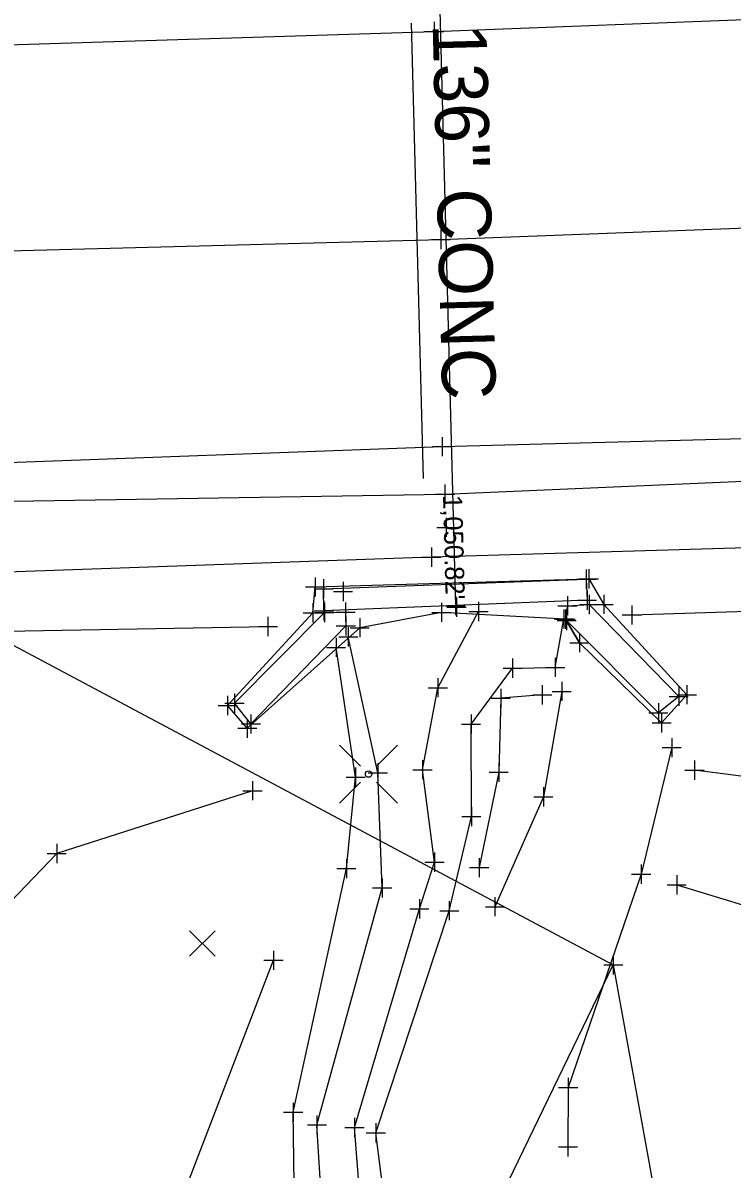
# Model space of a CAD drawing. Extents: x 211013 to 211654, y 505587 to 505872.
# Drawn here: x 211288.2 to 211325.2, y 505674.5 to 505734.3 of the extents above; entities that cross this region are included whole.
import ezdxf

# ---------------------------------------------------------------- set-up
doc = ezdxf.new("R2010")
doc.units = 0
for name, color, linetype in [('_CIVIL_CONSTRUCTION', 7, 'Continuous'), ('AP_P_PCI_Pavement', 7, 'Continuous'), ('BR_P_Gen_Porous_Backfill', 7, 'Continuous'), ('BR_X_Rail_Centerline', 7, 'Continuous'), ('DR_X_Storm_Sewer', 7, 'Continuous'), ('DR_X_Text', 7, 'Continuous'), ('DV_X_Property_Line', 7, 'Continuous'), ('DV_X_Section_VMS_Line', 7, 'Continuous'), ('GE_X_Alignment_1000_Curve_Data', 7, 'Continuous'), ('GE_X_Alignment_100_Stations', 7, 'Continuous'), ('GE_X_Alignment_500_Curve_Data', 7, 'Continuous'), ('GE_X_Alignment_500_Stations', 7, 'Continuous'), ('PM_X_CL_Pass_Proh_Lt', 7, 'Continuous'), ('PM_X_Edge_Line', 7, 'Continuous'), ('RW_P_Esmt_SH', 7, 'Continuous'), ('RW_X_Esmt_SH', 7, 'Continuous'), ('SC_Scratch1', 7, 'Continuous'), ('SC_Scratch10', 7, 'Continuous'), ('SC_Scratch3', 7, 'Continuous'), ('SV_X_Terrain_Break_Line', 7, 'Continuous')]:
    doc.layers.add(name, color=color, linetype=linetype)

msp = doc.modelspace()

# ---------------------------------------------------------------- linework, layer by layer
at = {"layer": '_CIVIL_CONSTRUCTION'}
msp.add_lwpolyline([(211299.916, 505697.512), (211298.892, 505698.697), (211303.335, 505703.534), (211303.459, 505704.883), (211317.723, 505705.313), (211318.503, 505703.976), (211322.84, 505699.265), (211321.522, 505697.798), (211317.242, 505701.978), (211316.512, 505703.201), (211310.041, 505703.559), (211305.778, 505702.757)], close=True, dxfattribs=at)
at = {"layer": 'AP_P_PCI_Pavement'}
for points in [[(211268.661, 505610.595), (211277.693, 505622.388), (211291.679, 505636.827), (211300.374, 505649.703), (211302.563, 505658.8), (211302.312, 505677.481), (211305.082, 505690.193), (211305.564, 505694.97), (211304.545, 505701.731)], [(211278.617, 505602.944), (211284.156, 505615.606), (211296.4, 505628.157), (211306.009, 505644.49), (211310.431, 505653.543), (211313.281, 505673.354), (211319.004, 505685.175)]]:
    msp.add_lwpolyline(points, dxfattribs=at)
at = {"layer": 'BR_P_Gen_Porous_Backfill'}
msp.add_lwpolyline([(211014.599, 505713.748), (211060.117, 505715.292), (211110.477, 505716.76), (211159.605, 505717.981), (211200.363, 505719.769), (211209.599, 505719.607), (211259.602, 505721.26), (211285.444, 505722.36), (211310.014, 505723.011), (211334.642, 505723.955), (211359.491, 505724.699), (211409.159, 505726.492), (211459.682, 505727.943), (211509.305, 505729.663), (211559.474, 505731.149), (211610.495, 505732.771), (211648.152, 505734.06)], dxfattribs=at)
at = {"layer": 'BR_X_Rail_Centerline'}
for p, q in [((211286.353, 505702.567), (211319.004, 505685.175)), ((211319.004, 505685.175), (211322.15, 505667.715))]:
    msp.add_line(p, q, dxfattribs=at)
at = {"layer": 'DR_X_Storm_Sewer'}
msp.add_line((211309.709, 505744.552), (211310.772, 505703.905), dxfattribs=at)
at = {"layer": 'DR_X_Text'}
msp.add_line((211309.098, 505710.538), (211308.477, 505734.29), dxfattribs=at)
at = {"layer": 'DV_X_Property_Line'}
for p, q in [((211335.584, 505707.206), (211309.514, 505706.438)), ((211309.514, 505706.438), (211285.253, 505705.579))]:
    msp.add_line(p, q, dxfattribs=at)
at = {"layer": 'DV_X_Section_VMS_Line'}
for p, q in [((211309.664, 505734.365), (211309.664, 505733.365)), ((211309.664, 505734.365), (211309.664, 505733.365)), ((211309.164, 505733.865), (211310.164, 505733.865)), ((211309.164, 505733.865), (211310.164, 505733.865)), ((211309.664, 505733.865), (211309.664, 505733.865)), ((211309.664, 505733.865), (211309.664, 505733.865)), ((211310.014, 505723.511), (211310.014, 505722.511)), ((211310.014, 505723.511), (211310.014, 505722.511)), ((211309.514, 505723.011), (211310.514, 505723.011)), ((211309.514, 505723.011), (211310.514, 505723.011)), ((211310.014, 505723.011), (211310.014, 505723.011)), ((211310.014, 505723.011), (211310.014, 505723.011)), ((211310.077, 505712.707), (211310.077, 505711.707)), ((211310.077, 505712.707), (211310.077, 505711.707)), ((211309.577, 505712.207), (211310.577, 505712.207)), ((211309.577, 505712.207), (211310.577, 505712.207)), ((211310.077, 505712.207), (211310.077, 505712.207)), ((211310.077, 505712.207), (211310.077, 505712.207)), ((211310.225, 505710.223), (211310.225, 505709.223)), ((211309.725, 505709.723), (211310.725, 505709.723)), ((211310.225, 505709.723), (211310.225, 505709.723)), ((211310.292, 505708.492), (211310.292, 505707.492)), ((211309.792, 505707.992), (211310.792, 505707.992)), ((211310.292, 505707.992), (211310.292, 505707.992)), ((211309.514, 505706.938), (211309.514, 505705.938)), ((211309.014, 505706.438), (211310.014, 505706.438)), ((211309.514, 505706.438), (211309.514, 505706.438)), ((211303.459, 505705.383), (211303.459, 505704.383)), ((211303.897, 505705.288), (211303.897, 505704.288)), ((211317.088, 505705.295), (211318.088, 505705.295)), ((211317.223, 505705.313), (211318.223, 505705.313)), ((211317.588, 505705.795), (211317.588, 505704.795)), ((211317.588, 505705.295), (211317.588, 505705.295)), ((211317.723, 505705.813), (211317.723, 505704.813)), ((211317.723, 505705.313), (211317.723, 505705.313)), ((211302.959, 505704.883), (211303.959, 505704.883)), ((211303.397, 505704.788), (211304.397, 505704.788)), ((211303.459, 505704.883), (211303.459, 505704.883)), ((211303.897, 505704.788), (211303.897, 505704.788)), ((211304.908, 505705.149), (211304.908, 505704.149)), ((211317.633, 505704.698), (211317.633, 505703.698)), ((211303.907, 505704.142), (211303.907, 505703.142)), ((211304.408, 505704.649), (211305.408, 505704.649)), ((211304.908, 505704.649), (211304.908, 505704.649)), ((211310.824, 505704.334), (211310.824, 505703.334)), ((211311.977, 505704.105), (211311.977, 505703.105)), ((211316.61, 505704.406), (211316.61, 505703.406)), ((211317.133, 505704.198), (211318.133, 505704.198)), ((211317.633, 505704.198), (211317.633, 505704.198)), ((211317.752, 505704.471), (211317.752, 505703.471)), ((211318.503, 505704.476), (211318.503, 505703.476)), ((211302.835, 505703.534), (211303.835, 505703.534)), ((211303.335, 505704.034), (211303.335, 505703.034)), ((211303.335, 505703.534), (211303.335, 505703.534)), ((211303.407, 505703.642), (211304.407, 505703.642)), ((211303.45, 505703.556), (211304.45, 505703.556)), ((211303.907, 505703.642), (211303.907, 505703.642)), ((211303.95, 505704.056), (211303.95, 505703.056)), ((211303.95, 505703.556), (211303.95, 505703.556)), ((211304.533, 505703.568), (211305.533, 505703.568)), ((211305.033, 505704.068), (211305.033, 505703.068)), ((211305.033, 505703.568), (211305.033, 505703.568)), ((211309.541, 505703.559), (211310.541, 505703.559)), ((211310.041, 505704.059), (211310.041, 505703.059)), ((211310.041, 505703.559), (211310.041, 505703.559)), ((211310.324, 505703.834), (211311.324, 505703.834)), ((211310.824, 505703.834), (211310.824, 505703.834)), ((211311.477, 505703.605), (211312.477, 505703.605)), ((211311.977, 505703.605), (211311.977, 505703.605)), ((211316.11, 505703.906), (211317.11, 505703.906)), ((211316.416, 505703.715), (211316.416, 505702.715)), ((211316.512, 505703.701), (211316.512, 505702.701)), ((211316.568, 505703.629), (211316.568, 505702.629)), ((211316.61, 505703.906), (211316.61, 505703.906)), ((211317.252, 505703.971), (211318.252, 505703.971)), ((211317.752, 505703.971), (211317.752, 505703.971)), ((211318.003, 505703.976), (211319.003, 505703.976)), ((211318.503, 505703.976), (211318.503, 505703.976)), ((211319.968, 505703.925), (211319.968, 505702.925)), ((211300.992, 505703.322), (211300.992, 505702.322)), ((211305.058, 505703.35), (211305.058, 505702.35)), ((211305.778, 505703.257), (211305.778, 505702.257)), ((211315.916, 505703.215), (211316.916, 505703.215)), ((211316.012, 505703.201), (211317.012, 505703.201)), ((211316.068, 505703.129), (211317.068, 505703.129)), ((211316.416, 505703.215), (211316.416, 505703.215)), ((211316.512, 505703.201), (211316.512, 505703.201)), ((211316.568, 505703.129), (211316.568, 505703.129)), ((211319.468, 505703.425), (211320.468, 505703.425)), ((211319.968, 505703.425), (211319.968, 505703.425)), ((211300.492, 505702.822), (211301.492, 505702.822)), ((211300.992, 505702.822), (211300.992, 505702.822)), ((211304.558, 505702.85), (211305.558, 505702.85)), ((211305.058, 505702.85), (211305.058, 505702.85)), ((211305.183, 505702.782), (211305.183, 505701.782)), ((211305.278, 505702.757), (211306.278, 505702.757)), ((211305.778, 505702.757), (211305.778, 505702.757)), ((211317.242, 505702.478), (211317.242, 505701.478)), ((211304.045, 505701.731), (211305.045, 505701.731)), ((211304.545, 505702.231), (211304.545, 505701.231)), ((211304.545, 505701.731), (211304.545, 505701.731)), ((211304.683, 505702.282), (211305.683, 505702.282)), ((211305.183, 505702.282), (211305.183, 505702.282)), ((211316.742, 505701.978), (211317.742, 505701.978)), ((211317.242, 505701.978), (211317.242, 505701.978)), ((211313.752, 505701.151), (211313.752, 505700.151)), ((211315.976, 505701.191), (211315.976, 505700.191)), ((211313.252, 505700.651), (211314.252, 505700.651)), ((211313.752, 505700.651), (211313.752, 505700.651)), ((211315.476, 505700.691), (211316.476, 505700.691)), ((211315.976, 505700.691), (211315.976, 505700.691)), ((211309.856, 505700.129), (211309.856, 505699.129)), ((211316.314, 505699.937), (211316.314, 505698.937)), ((211299.25, 505699.322), (211299.25, 505698.322)), ((211309.356, 505699.629), (211310.356, 505699.629)), ((211309.856, 505699.629), (211309.856, 505699.629)), ((211313.131, 505699.577), (211313.131, 505698.577)), ((211315.3, 505699.755), (211315.3, 505698.755)), ((211315.814, 505699.437), (211316.814, 505699.437)), ((211316.314, 505699.437), (211316.314, 505699.437)), ((211322.413, 505699.677), (211322.413, 505698.677)), ((211322.84, 505699.765), (211322.84, 505698.765)), ((211298.75, 505698.822), (211299.75, 505698.822)), ((211298.892, 505699.197), (211298.892, 505698.197)), ((211299.25, 505698.822), (211299.25, 505698.822)), ((211312.631, 505699.077), (211313.631, 505699.077)), ((211313.131, 505699.077), (211313.131, 505699.077)), ((211314.8, 505699.255), (211315.8, 505699.255)), ((211315.3, 505699.255), (211315.3, 505699.255)), ((211321.354, 505698.82), (211321.354, 505697.82)), ((211321.913, 505699.177), (211322.913, 505699.177)), ((211322.34, 505699.265), (211323.34, 505699.265)), ((211322.413, 505699.177), (211322.413, 505699.177)), ((211322.84, 505699.265), (211322.84, 505699.265)), ((211298.392, 505698.697), (211299.392, 505698.697)), ((211298.892, 505698.697), (211298.892, 505698.697)), ((211300.106, 505698.239), (211300.106, 505697.239)), ((211311.583, 505698.233), (211311.583, 505697.233)), ((211320.854, 505698.32), (211321.854, 505698.32)), ((211321.354, 505698.32), (211321.354, 505698.32)), ((211321.522, 505698.298), (211321.522, 505697.298)), ((211299.416, 505697.512), (211300.416, 505697.512)), ((211299.606, 505697.739), (211300.606, 505697.739)), ((211299.916, 505698.012), (211299.916, 505697.012)), ((211299.916, 505697.512), (211299.916, 505697.512)), ((211300.106, 505697.739), (211300.106, 505697.739)), ((211311.083, 505697.733), (211312.083, 505697.733)), ((211311.583, 505697.733), (211311.583, 505697.733)), ((211321.022, 505697.798), (211322.022, 505697.798)), ((211321.522, 505697.798), (211321.522, 505697.798)), ((211322.047, 505697.005), (211322.047, 505696.005)), ((211321.547, 505696.505), (211322.547, 505696.505)), ((211322.047, 505696.505), (211322.047, 505696.505)), ((211309.052, 505695.852), (211309.052, 505694.852)), ((211313.027, 505695.718), (211313.027, 505694.718)), ((211323.24, 505695.828), (211323.24, 505694.828)), ((211305.564, 505695.47), (211305.564, 505694.47)), ((211306.226, 505695.195), (211307.226, 505695.195)), ((211306.726, 505695.695), (211306.726, 505694.695)), ((211306.726, 505695.195), (211306.726, 505695.195)), ((211308.552, 505695.352), (211309.552, 505695.352)), ((211309.052, 505695.352), (211309.052, 505695.352)), ((211312.527, 505695.218), (211313.527, 505695.218)), ((211313.027, 505695.218), (211313.027, 505695.218)), ((211322.74, 505695.328), (211323.74, 505695.328)), ((211323.24, 505695.328), (211323.24, 505695.328)), ((211300.189, 505694.755), (211300.189, 505693.755)), ((211305.064, 505694.97), (211306.064, 505694.97)), ((211305.564, 505694.97), (211305.564, 505694.97)), ((211299.689, 505694.255), (211300.689, 505694.255)), ((211300.189, 505694.255), (211300.189, 505694.255)), ((211314.855, 505693.94), (211315.855, 505693.94)), ((211315.355, 505694.44), (211315.355, 505693.44)), ((211315.355, 505693.94), (211315.355, 505693.94)), ((211311.603, 505693.404), (211311.603, 505692.404)), ((211311.103, 505692.904), (211312.103, 505692.904)), ((211311.603, 505692.904), (211311.603, 505692.904)), ((211289.479, 505690.984), (211290.479, 505690.984)), ((211289.979, 505691.484), (211289.979, 505690.484)), ((211289.979, 505690.984), (211289.979, 505690.984)), ((211309.682, 505691.026), (211309.682, 505690.026)), ((211305.082, 505690.693), (211305.082, 505689.693)), ((211309.182, 505690.526), (211310.182, 505690.526)), ((211309.682, 505690.526), (211309.682, 505690.526)), ((211312.009, 505690.744), (211312.009, 505689.744)), ((211320.459, 505690.403), (211320.459, 505689.403)), ((211304.582, 505690.193), (211305.582, 505690.193)), ((211305.082, 505690.193), (211305.082, 505690.193)), ((211311.509, 505690.244), (211312.509, 505690.244)), ((211312.009, 505690.244), (211312.009, 505690.244)), ((211319.959, 505689.903), (211320.959, 505689.903)), ((211320.459, 505689.903), (211320.459, 505689.903)), ((211322.311, 505689.843), (211322.311, 505688.843)), ((211306.447, 505689.181), (211307.447, 505689.181)), ((211306.947, 505689.681), (211306.947, 505688.681)), ((211306.947, 505689.181), (211306.947, 505689.181)), ((211321.811, 505689.343), (211322.811, 505689.343)), ((211322.311, 505689.343), (211322.311, 505689.343)), ((211308.888, 505688.595), (211308.888, 505687.595)), ((211312.833, 505688.705), (211312.833, 505687.705)), ((211308.388, 505688.095), (211309.388, 505688.095)), ((211308.888, 505688.095), (211308.888, 505688.095)), ((211309.952, 505687.996), (211310.952, 505687.996)), ((211310.452, 505688.496), (211310.452, 505687.496)), ((211310.452, 505687.996), (211310.452, 505687.996)), ((211312.333, 505688.205), (211313.333, 505688.205)), ((211312.833, 505688.205), (211312.833, 505688.205)), ((211301.283, 505685.911), (211301.283, 505684.911)), ((211319.004, 505685.675), (211319.004, 505684.675)), ((211300.783, 505685.411), (211301.783, 505685.411)), ((211301.283, 505685.411), (211301.283, 505685.411)), ((211318.504, 505685.175), (211319.504, 505685.175)), ((211319.004, 505685.175), (211319.004, 505685.175)), ((211316.652, 505679.278), (211316.652, 505678.278)), ((211316.152, 505678.778), (211317.152, 505678.778)), ((211316.652, 505678.778), (211316.652, 505678.778)), ((211302.312, 505677.981), (211302.312, 505676.981)), ((211301.812, 505677.481), (211302.812, 505677.481)), ((211302.312, 505677.481), (211302.312, 505677.481)), ((211303.549, 505677.317), (211303.549, 505676.317)), ((211305.511, 505677.184), (211305.511, 505676.184)), ((211303.049, 505676.817), (211304.049, 505676.817)), ((211303.549, 505676.817), (211303.549, 505676.817)), ((211305.011, 505676.684), (211306.011, 505676.684)), ((211305.511, 505676.684), (211305.511, 505676.684)), ((211306.622, 505676.904), (211306.622, 505675.904)), ((211306.122, 505676.404), (211307.122, 505676.404)), ((211306.622, 505676.404), (211306.622, 505676.404)), ((211316.64, 505676.18), (211316.64, 505675.18)), ((211316.14, 505675.68), (211317.14, 505675.68)), ((211316.64, 505675.68), (211316.64, 505675.68))]:
    msp.add_line(p, q, dxfattribs=at)
at = {"layer": 'GE_X_Alignment_1000_Curve_Data'}
msp.add_lwpolyline([(211273.121, 505606.086), (211279.731, 505619.542), (211294.465, 505632.777), (211303.74, 505647.431), (211307.255, 505654.162), (211305.511, 505676.684), (211308.888, 505688.095), (211309.682, 505690.526), (211309.052, 505695.352), (211309.856, 505699.629), (211311.977, 505703.605)], dxfattribs=at)
at = {"layer": 'GE_X_Alignment_100_Stations'}
msp.add_line((211316.512, 505703.201), (211317.242, 505701.978), dxfattribs=at)
for points in [[(211647.318, 505706.799), (211627.344, 505705.682), (211610.092, 505706.34), (211575.017, 505706.539), (211552.648, 505705.843), (211519.602, 505699.232), (211499.135, 505697.96), (211475.775, 505696.23), (211461, 505699.162), (211420.091, 505696.365), (211400.739, 505694.843), (211371.166, 505695.886), (211354.307, 505694.819), (211334.256, 505693.898), (211323.24, 505695.328)], [(211319.968, 505703.425), (211335.359, 505703.922), (211358.547, 505705.427)], [(211213.935, 505701.665), (211234.368, 505701.356), (211259.558, 505702.48), (211286.353, 505702.567), (211300.992, 505702.822)], [(211316.314, 505699.437), (211315.355, 505693.94), (211312.833, 505688.205)], [(211315.3, 505699.255), (211313.131, 505699.077), (211313.027, 505695.218), (211312.009, 505690.244)], [(211322.047, 505696.505), (211320.459, 505689.903), (211316.652, 505678.778), (211316.64, 505675.68)], [(211300.189, 505694.255), (211289.979, 505690.984), (211282.308, 505682.988), (211268.748, 505680.552), (211247.685, 505678.308), (211236.738, 505676.753), (211227.288, 505673.299), (211219.174, 505669.2), (211212.291, 505658.054), (211212.19, 505645.024), (211215.908, 505636.829), (211217.344, 505628.443), (211218.512, 505613.393)], [(211322.311, 505689.343), (211333.961, 505685.806), (211349.341, 505686.838)], [(211281.328, 505628.196), (211283.332, 505634.721), (211288.956, 505646.146), (211290.89, 505656.543), (211295.544, 505670.479), (211301.283, 505685.411)]]:
    msp.add_lwpolyline(points, dxfattribs=at)
at = {"layer": 'GE_X_Alignment_500_Curve_Data'}
for points in [[(211014.945, 505724.377), (211059.004, 505725.803), (211109.78, 505727.197), (211159.509, 505728.763), (211208.815, 505730.577), (211259.797, 505732.066), (211285.147, 505733.092), (211309.664, 505733.865), (211334.856, 505734.829), (211359.193, 505735.686), (211410.228, 505737.375), (211459.705, 505738.838), (211509.757, 505740.373), (211559.969, 505741.955), (211609.77, 505743.952), (211648.342, 505745.167)], [(211015.177, 505702.304), (211059.888, 505703.863), (211110.083, 505705.463), (211159.907, 505707.213), (211209.998, 505708.767), (211260.133, 505710.635), (211285.525, 505711.304), (211310.077, 505712.207), (211335.574, 505712.892), (211359.345, 505713.874), (211409.235, 505715.384), (211460.17, 505716.905), (211509.667, 505718.762), (211560, 505720.306), (211609.437, 505722.106), (211648.414, 505723.359)]]:
    msp.add_lwpolyline(points, dxfattribs=at)
at = {"layer": 'GE_X_Alignment_500_Stations'}
msp.add_lwpolyline([(211015.256, 505700.037), (211059.934, 505701.398), (211110.755, 505702.874), (211160.108, 505704.521), (211209.982, 505706.264), (211260.298, 505708.404), (211285.531, 505709.322), (211310.225, 505709.723), (211335.79, 505710.841), (211359.802, 505710.904), (211409.556, 505712.881), (211460.495, 505714.505), (211509.532, 505715.913), (211559.916, 505717.474), (211609.342, 505719.659), (211648.637, 505720.819)], dxfattribs=at)
at = {"layer": 'PM_X_CL_Pass_Proh_Lt'}
msp.add_lwpolyline([(211204.733, 505719.498), (211209.599, 505719.607), (211259.602, 505721.26), (211285.444, 505722.36), (211310.014, 505723.011), (211334.642, 505723.955), (211359.491, 505724.699), (211409.159, 505726.492), (211459.682, 505727.943), (211509.305, 505729.663), (211559.474, 505731.149), (211610.495, 505732.771), (211648.152, 505734.06)], dxfattribs=at)
at = {"layer": 'PM_X_Edge_Line'}
for points in [[(211014.945, 505724.377), (211059.004, 505725.803), (211109.78, 505727.197), (211159.509, 505728.763), (211208.815, 505730.577), (211259.797, 505732.066), (211285.147, 505733.092), (211309.664, 505733.865), (211334.856, 505734.829), (211359.193, 505735.686), (211410.228, 505737.375), (211459.705, 505738.838), (211509.757, 505740.373), (211559.969, 505741.955), (211609.77, 505743.952), (211648.342, 505745.167)], [(211015.177, 505702.304), (211059.888, 505703.863), (211110.083, 505705.463), (211159.907, 505707.213), (211209.998, 505708.767), (211260.133, 505710.635), (211285.525, 505711.304), (211310.077, 505712.207), (211335.574, 505712.892), (211359.345, 505713.874), (211409.235, 505715.384), (211460.17, 505716.905), (211509.667, 505718.762), (211560, 505720.306), (211609.437, 505722.106), (211648.414, 505723.359)]]:
    msp.add_lwpolyline(points, dxfattribs=at)
at = {"layer": 'RW_P_Esmt_SH'}
for points in [[(211277.217, 505605.247), (211283.503, 505616.58), (211295.885, 505629.207), (211305.092, 505644.914), (211309.482, 505653.832), (211306.622, 505676.404), (211310.452, 505687.996), (211311.603, 505692.904), (211311.583, 505697.733), (211313.752, 505700.651), (211315.976, 505700.691), (211316.416, 505703.215)], [(211269.724, 505609.085), (211278.034, 505621.104), (211292.882, 505634.845), (211301.288, 505647.763), (211304.833, 505656.166), (211303.549, 505676.817), (211306.947, 505689.181), (211306.726, 505695.195), (211305.183, 505702.282)]]:
    msp.add_lwpolyline(points, dxfattribs=at)
at = {"layer": 'RW_X_Esmt_SH'}
for p, q in [((211296.904, 505685.617), (211298.238, 505686.952)), ((211296.904, 505686.952), (211298.238, 505685.617))]:
    msp.add_line(p, q, dxfattribs=at)
at = {"layer": 'SC_Scratch1'}
for p, q in [((211310.772, 505704.405), (211310.772, 505703.405)), ((211310.272, 505703.905), (211311.272, 505703.905)), ((211310.772, 505703.905), (211310.772, 505703.905))]:
    msp.add_line(p, q, dxfattribs=at)
at = {"layer": 'SC_Scratch10'}
for points in [[(211303.907, 505703.642), (211303.897, 505704.788), (211317.588, 505705.295), (211317.633, 505704.198)], [(211300.106, 505697.739), (211299.25, 505698.822), (211303.95, 505703.556), (211305.033, 505703.568), (211305.058, 505702.85)], [(211316.568, 505703.129), (211316.61, 505703.906), (211317.752, 505703.971), (211322.413, 505699.177), (211321.354, 505698.32)]]:
    msp.add_lwpolyline(points, close=True, dxfattribs=at)
at = {"layer": 'SC_Scratch3'}
for p, q in [((211304.731, 505696.628), (211305.825, 505695.535)), ((211306.658, 505695.535), (211307.75, 505696.628)), ((211304.731, 505693.61), (211305.825, 505694.703)), ((211306.658, 505694.703), (211307.75, 505693.61))]:
    msp.add_line(p, q, dxfattribs=at)
msp.add_circle((211306.242, 505695.125), 0.17, dxfattribs=at)
at = {"layer": 'SV_X_Terrain_Break_Line'}
msp.add_line((211303.459, 505704.883), (211317.723, 505705.313), dxfattribs=at)
for points in [[(211317.723, 505705.313), (211318.503, 505703.976), (211322.84, 505699.265)], [(211298.892, 505698.697), (211303.335, 505703.534), (211303.459, 505704.883)]]:
    msp.add_lwpolyline(points, dxfattribs=at)

# ---------------------------------------------------------------- texts
at = {"layer": 'DR_X_Text'}
msp.add_text('136" CONC', height=2.8, rotation=271.49809, dxfattribs=at).set_placement((211309.58, 505734.254))
at = {"layer": 'SC_Scratch1'}
msp.add_text("1,050.82'", height=1, rotation=271.49809, dxfattribs=at).set_placement((211310.121, 505709.671))

doc.saveas('drawing.dxf')
